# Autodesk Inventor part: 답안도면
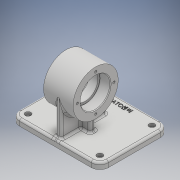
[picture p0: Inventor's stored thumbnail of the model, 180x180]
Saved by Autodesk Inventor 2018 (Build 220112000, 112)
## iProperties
Created: 2019-09
Part Number: 답안도면
Material: 일반
Document SubType Name: Modeling
Designer: USER
Density: 1 g/cm^3
Appearance: 기본값
Author: USER
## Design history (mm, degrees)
sketch "스케치1"
  geometry: L1 (0, 0)-(42, 0); L2 (0, 0)-(0, 32); L3 (0, 32)-(42, 32); L4 (42, 32)-(42, 0); L5 (0, 21)-(15, 21); L6 (15, 21)-(15, 18); L7 (15, 18)-(27, 18); L8 (27, 18)-(27, 21); L9 (27, 21)-(42, 21)
  constraints: 18 end point, 4 perpendicular, 4 point on line, 3 horizontal, 1 vertical
  dimensions: "d0" = 42 distance of L1.start L1.end; "d1" = 42 diameter of L5 L1; "d2" = 64 diameter of L3 L1; "d3" = 36 diameter of L7 L1; "d4" = 15 distance between parallel lines of L2 L6; "d5" = 15 distance between parallel lines of L4 L8
revolve "회전1" sketch "스케치1" stored, may be unused: angle "d6" = 90 deg
node "작업 평면1"
sketch "스케치2"
  geometry: L1 (0, 32)-(42, 32) reference; L2 (21, 32)-(21, -32); L3 (0, -32)-(42, -32) reference; L4 (42, -21)-(42, 21) reference; L5 (0, -21)-(0, 21) reference; L6 (0, 0)-(42, 0); L7 (21, 0)-(84, 0); L8 (84, 0)-(84, 62); L9 (84, 62)-(-42, 62); L10 (-42, 62)-(-42, -36); L11 (-42, -36)-(84, -36); L12 (84, -36)-(84, 0); 2 further points
  constraints: 16 end point, 5 midpoint, 3 perpendicular, 1 point on line, 1 vertical
  dimensions: "d8" = 63 distance of L7.start L7.end; "d9" = 62 distance of L7.end L8.end; "d10" = 126 distance of L8.end L9.end; "d11" = 98 distance of L9.end L10.end; "d12" = 126 distance of L10.end L11.end
extrude "돌출1" join sketch "스케치2" distance "d13" = 9; taper "d14" = 0 deg
sketch "스케치3"
  geometry: L1 (0, -32)-(-42, -32) reference; L2 (-21, -32)-(-21, -50); L3 (-21, -50)-(-4, -50); L4 (-4, -50)-(-4, -32); L5 (-21, -50)-(-38, -50); L6 (-38, -50)-(-38, -32); L7 (-4, -32)-(-38, -32); L8 (-4, -32)-(-4, -28.095); L9 (-4, -28.095)-(-38, -28.095); L10 (-38, -28.095)-(-38, -32); 1 further point
  constraints: 18 end point, 4 perpendicular, 2 point on line, 1 collinear, 1 midpoint, 1 vertical
  dimensions: "d15" = 17 distance of L2.end L3.end; "d16" = 17 distance of L2.end L5.end
extrude "돌출2" join sketch "스케치3" stored distance "d17" = 8; taper "d18" = 0 deg
node "작업 평면2"
sketch "스케치4"
  geometry: L1 (62, -50)-(-36, -50) reference; L2 (62, -59)-(-36, -59) reference; L3 (-36, -59)-(-36, -50) reference; L4 (62, -50)-(-36, -50) reference; L5 (62, -59)-(62, -50) reference; L6 (32, 0)-(32, -50); L7 (-32, 0)-(-32, -50); L8 (32, -50)-(-32, -50); C1 r 32 at (0, 0) reference; A1 r 32 centre (0, 0) between (32, 0) and (-32, 0) reference; 1 further point
  constraints: 6 end point, 4 tangent, 2 perpendicular, 2 point on circle, 2 point on line, 1 collinear
feature "리브1" sketch "스케치4" dims "d19" = 1, "d20" = 8, "d21" = 0, "d22" = 0, "d23" = 1, "d24" = 1
sketch "스케치5"
  geometry: L1 (-42, 62)-(-42, -36) reference; L2 (-42, 13)-(84, 13); L3 (84, -36)-(84, 62) reference; L4 (-42, 13)-(-42, 50); L5 (84, 62)-(-42, 62) reference; L6 (21, 62)-(-30, 62); L7 (-30, 62)-(-30, 37.273); L8 (-42, 50)-(-24.665, 50); L9 (-42, 13)-(-42, -24); L10 (-42, -36)-(84, -36) reference; L11 (21, -36)-(-30, -36); L12 (-30, -36)-(-30, -11.448); L13 (-42, -24)-(-22.22, -24); 3 further points
  constraints: 18 end point, 8 point on line, 4 midpoint, 2 horizontal, 2 perpendicular
  dimensions: "d25" = 37 distance of L2.start L4.end; "d26" = 51 distance of L6.start L6.end; "d27" = 37 distance of L2.start L9.end; "d28" = 51 distance of L11.start L11.end
hole "구멍1" sketch "스케치5" at (-30, 50), (-30, -24) diameter "d29" = 4.5; stored, may be unused: countersink angle "d33" = 90 deg, drill point angle "d35" = 118 deg; dims "d30" = 6, "d31" = 8, "d32" = 4.4, "d34" = 100
fillet "모깎기1" dims "d36" = 12
sketch "스케치6" dims "d37" = 52
  geometry: C1 r 21 at (0, 0) reference; 3 further points
  constraints: 2 horizontal alignment, 1 coincident, 2 other
hole "구멍2" sketch "스케치6" at (26, 0) diameter "d38" = 3.242; stored, may be unused: countersink angle "d42" = 90 deg, drill point angle "d44" = 118 deg; dims "d39" = 8, "d40" = 8, "d41" = 4.4, "d43" = 10
sketch "스케치7"
  geometry: L1 (84, -24)-(84, 50) reference; L2 (72, 62)-(-30, 62) reference; 2 further points
  constraints: 1 other
  dimensions: "d48" = 63 distance from line of L1 point (21, 52); "d49" = 10 distance from line of L2 point (21, 52)
feature "엠보싱1" sketch "스케치7" dims "d0" = 42, "d1" = 42, "d2" = 64, "d3" = 36, "d4" = 15, "d5" = 15, "d50" = 0.5, "d51" = 0
fillet "모깎기2" dims "d52" = 0.3
chamfer "모따기1" distance "d53" = 1; stored, may be unused: second distance "d54" = 2, angle "d55" = 45 deg
fillet "모깎기3" dims "d56" = 3
fillet "모깎기4" dims "d57" = 3
fillet "모깎기5" dims "d58" = 3
node "작업 평면3"
node "솔리드1"
pattern_circular "원형 패턴1" dims angle "d46" = 360 deg
mirror "미러1"
mirror "미러2"
node "투영된 루프1"
other parameters: "d7" = -59
